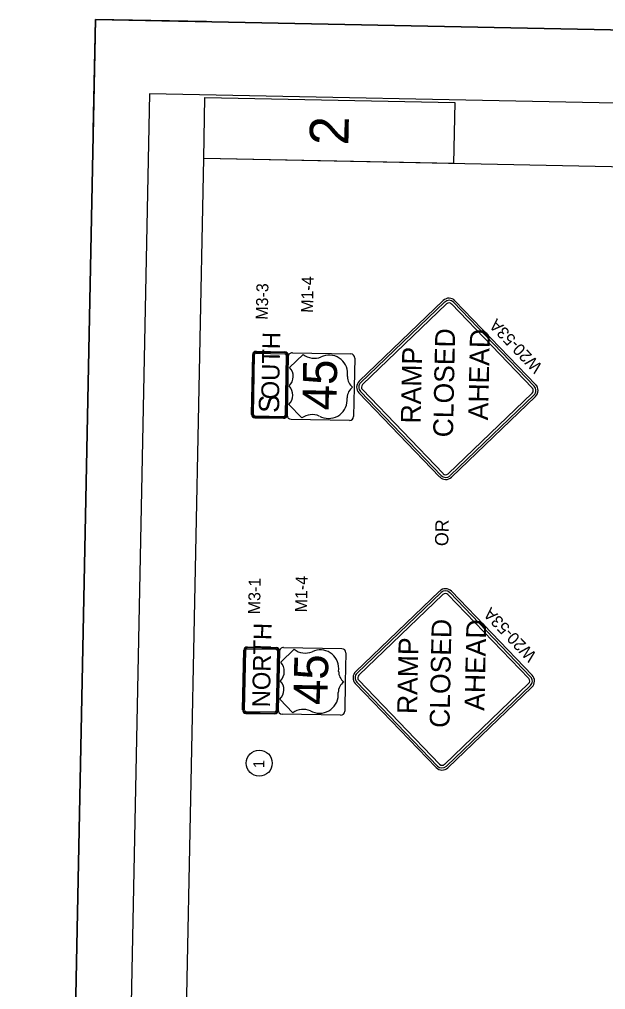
# Model space of a CAD drawing. Extents: x 345549 to 379569, y 127949 to 230467.
# Drawn here: x 345549 to 353466, y 217351 to 230467 of the extents above; entities that cross this region are included whole.
import ezdxf

# ---------------------------------------------------------------- set-up
doc = ezdxf.new("R2010")
doc.units = 0
for name, color, linetype in [('CA-TEXT', 7, 'Continuous'), ('P_RDWY_Text', 7, 'Continuous'), ('P_SGN_Cell', 7, 'Continuous'), ('PLT_Sheet_Border', 7, 'Continuous'), ('PLT_Sheet_Info', 7, 'Continuous')]:
    doc.layers.add(name, color=color, linetype=linetype)

msp = doc.modelspace()

# ---------------------------------------------------------------- linework, layer by layer
at = {"layer": 'CA-TEXT'}
msp.add_circle((348788, 220412), 176, dxfattribs=at)
at = {"layer": 'P_RDWY_Text'}
msp.add_lwpolyline([(345549, 179477), (346576, 230467), (379569, 229803), (378542, 178813)], close=True, dxfattribs=at)
at = {"layer": 'P_SGN_Cell'}
for p, q in [((348684, 225127), (348700, 225937)), ((348695, 225127), (348711, 225937)), ((348710, 225127), (348726, 225937)), ((348745, 225955), (349135, 225947)), ((348746, 225981), (349136, 225974)), ((348746, 225970), (349136, 225962)), ((349154, 225928), (349137, 225118)), ((349169, 225928), (349152, 225118)), ((349180, 225928), (349164, 225118)), ((349164, 225118), (349180, 225905)), ((349380, 225936), (349198, 225761)), ((349237, 225960), (350024, 225944)), ((350079, 225887), (350071, 225493)), ((350079, 225887), (350079, 225887)), ((349981, 225638), (349982, 225674)), ((350071, 225493), (350063, 225100)), ((349975, 225317), (349975, 225352)), ((349188, 225261), (349362, 225079)), ((348728, 225108), (349118, 225100)), ((348728, 225093), (349118, 225085)), ((348728, 225082), (349118, 225074)), ((350006, 225045), (349219, 225060)), ((348563, 221131), (348580, 221941)), ((348575, 221131), (348591, 221941)), ((348590, 221131), (348606, 221941)), ((348625, 221974), (349015, 221966)), ((348625, 221959), (349015, 221951)), ((348626, 221985), (349016, 221977)), ((349033, 221932), (349017, 221122)), ((349048, 221932), (349032, 221122)), ((349060, 221931), (349043, 221122)), ((349260, 221951), (349078, 221776)), ((349117, 221975), (349904, 221960)), ((349044, 221133), (349059, 221920)), ((349959, 221902), (349951, 221508)), ((349959, 221902), (349959, 221902)), ((349861, 221653), (349862, 221689)), ((349951, 221508), (349943, 221115)), ((349067, 221276), (349242, 221094)), ((349855, 221332), (349855, 221367)), ((348608, 221112), (348998, 221104)), ((348608, 221097), (348998, 221089)), ((348608, 221085), (348998, 221078)), ((349886, 221060), (349099, 221076))]:
    msp.add_line(p, q, dxfattribs=at)
for points in [[(351274, 226667), (350138, 225576)], [(352523, 225529), (351432, 226664)], [(351293, 226647), (350157, 225556)], [(351318, 226621), (350182, 225530)], [(352476, 225484), (351386, 226620)], [(352502, 225509), (351411, 226645)], [(350134, 225417), (351225, 224281)], [(350155, 225437), (351246, 224301)], [(350181, 225462), (351272, 224326)], [(351340, 224324), (352476, 225415)], [(351365, 224299), (352501, 225390)], [(351385, 224278), (352520, 225369)], [(351225, 222739), (350089, 221648)], [(351245, 222719), (350109, 221627)], [(352454, 221581), (351363, 222717)], [(352474, 221601), (351383, 222736)], [(351269, 222693), (350134, 221602)], [(352428, 221556), (351337, 222692)], [(350086, 221489), (351177, 220353)], [(350106, 221509), (351197, 220373)], [(350132, 221534), (351223, 220398)], [(351291, 220396), (352427, 221487)], [(351316, 220371), (352452, 221462)], [(351336, 220350), (352472, 221441)]]:
    msp.add_lwpolyline(points, dxfattribs=at)
for centre, radius, start, end in [((351351, 226586), 112, 43.8462, 133.8462), ((351351, 226586), 83.9, 43.8462, 133.8462), ((351351, 226586), 48.2, 43.8462, 133.8462), ((348745, 225936), 45, 88.8462, 178.8462), ((348745, 225936), 33.7, 88.8462, 178.8462), ((348745, 225936), 18.7, 88.8462, 178.8462), ((349135, 225929), 18.7, 358.8462, 88.8462), ((349135, 225929), 45, 358.8462, 88.8462), ((349135, 225929), 33.7, 358.8462, 88.8462), ((349236, 225904), 56.2, 88.8462, 178.8462), ((349530, 226136), 250, 233.1143, 291.9873), ((349732, 225679), 250, 358.8462, 115.6928), ((350023, 225888), 56.2, 358.8462, 88.8462), ((349068, 225639), 179, 314.4191, 43.2734), ((350162, 225635), 181, 179.1885, 231.634), ((349063, 225389), 179, 314.4191, 43.2734), ((350156, 225348), 181, 126.0584, 178.5039), ((350216, 225495), 112, 133.8443, 223.8462), ((350216, 225495), 83.9, 133.8443, 223.8462), ((350216, 225495), 48.2, 133.8443, 223.8462), ((352442, 225450), 48.2, 313.8534, 44.4971), ((352442, 225450), 83.9, 313.8534, 44.4971), ((352442, 225450), 112, 313.8534, 44.4971), ((349725, 225322), 250, 240.0981, 358.8463), ((348729, 225127), 45, 179.6119, 268.8462), ((348729, 225127), 33.7, 178.8462, 268.8462), ((348729, 225127), 18.7, 178.8462, 268.8462), ((349119, 225119), 33.7, 268.8462, 358.8462), ((349119, 225119), 18.7, 268.8462, 358.8462), ((349119, 225119), 45, 268.8462, 358.8462), ((349220, 225117), 56.2, 178.8462, 268.8462), ((349505, 224874), 250, 67.7159, 124.7982), ((350007, 225101), 56.2, 268.8462, 358.8462), ((351307, 224359), 83.9, 223.8462, 313.8462), ((351307, 224359), 48.2, 223.8462, 313.8462), ((351307, 224359), 112, 223.8462, 313.8462), ((351303, 222658), 112, 43.8462, 133.8462), ((351303, 222658), 83.9, 43.8462, 133.8462), ((351303, 222658), 48.2, 43.8462, 133.8462), ((348625, 221940), 45, 88.8462, 178.8462), ((348625, 221940), 33.7, 88.8462, 178.8462), ((348625, 221940), 18.7, 88.8462, 178.8462), ((349015, 221932), 33.7, 358.8462, 88.8462), ((349015, 221932), 18.7, 358.8462, 88.8462), ((349015, 221932), 45, 358.8462, 88.8462), ((349116, 221919), 56.2, 88.8462, 178.8462), ((349410, 222151), 250, 233.1143, 291.9873), ((349612, 221694), 250, 358.8462, 115.6928), ((349903, 221903), 56.2, 358.8462, 88.8462), ((348948, 221654), 179, 314.4191, 43.2734), ((350042, 221651), 181, 179.1885, 231.634), ((350167, 221567), 112, 133.8443, 223.8462), ((350167, 221567), 83.9, 133.8443, 223.8462), ((350167, 221567), 48.2, 133.8443, 223.8462), ((352394, 221522), 48.2, 313.8534, 44.4971), ((352394, 221522), 83.9, 313.8534, 44.4971), ((352394, 221522), 112, 313.8534, 44.4971), ((348942, 221404), 179, 314.4191, 43.2734), ((350036, 221363), 181, 126.0584, 178.5039), ((349605, 221337), 250, 240.0981, 358.8463), ((348609, 221130), 45, 179.6119, 268.8462), ((348609, 221130), 33.7, 178.8462, 268.8462), ((348609, 221130), 18.7, 178.8462, 268.8462), ((348998, 221123), 33.7, 268.8462, 358.8462), ((348998, 221123), 18.7, 268.8462, 358.8462), ((348998, 221123), 45, 268.8462, 358.8462), ((349100, 221132), 56.2, 178.8462, 268.8462), ((349385, 220889), 250, 67.7159, 124.7982), ((349887, 221116), 56.2, 268.8462, 358.8462), ((351258, 220431), 83.9, 223.8462, 313.8462), ((351258, 220431), 48.2, 223.8462, 313.8462), ((351258, 220431), 112, 223.8462, 313.8462)]:
    msp.add_arc(centre, radius, start, end, dxfattribs=at)
at = {"layer": 'PLT_Sheet_Border'}
for points in [[(378542, 178813), (379569, 229803), (346576, 230467), (345549, 179477)], [(377800, 179188), (378799, 228828), (347306, 229462), (346306, 179822)]]:
    msp.add_lwpolyline(points, close=True, dxfattribs=at)
at = {"layer": 'PLT_Sheet_Info'}
for p, q in [((346546, 228967), (346576, 230467)), ((348076, 230437), (346576, 230467)), ((347087, 181344), (348038, 228585)), ((378032, 227981), (348038, 228585))]:
    msp.add_line(p, q, dxfattribs=at)
msp.add_lwpolyline([(348038, 228585), (348055, 229410), (351429, 229342), (351413, 228517)], close=True, dxfattribs=at)

# ---------------------------------------------------------------- texts
at = {"layer": 'CA-TEXT'}
for s, height, p in [('OR', 180, (351341, 223345)), ('1', 150, (348856, 220345))]:
    msp.add_text(s, height=height, rotation=88.8468, dxfattribs=at).set_placement(p)
at = {"layer": 'P_SGN_Cell'}
for s, height, rotation, p in [('M1-4', 162, 88.8462, (349514, 226499)), ('M3-3', 162, 88.8462, (348903, 226405)), ('W20-53A', 162, 133.8462, (352624, 225780)), ('CLOSED', 267.9, 88.8462, (351405, 224815)), ('AHEAD', 267.9, 88.8462, (351879, 225046)), ('OUTH', 240, 88.8462, (349055, 225329)), ('RAMP', 267.9, 88.8462, (350968, 225002)), ('45', 460, 88.8462, (349829, 225180)), ('S', 274, 88.8462, (349055, 225145)), ('M3-1', 162, 88.8462, (348799, 222423)), ('M1-4', 162, 88.8462, (349433, 222449)), ('W20-53A', 162, 133.8462, (352545, 221877)), ('CLOSED', 267.9, 88.8462, (351357, 220887)), ('AHEAD', 267.9, 88.8462, (351830, 221118)), ('NORTH', 240, 88.8462, (348932, 221165)), ('RAMP', 267.9, 88.8462, (350919, 221074)), ('45', 460, 88.8462, (349709, 221195))]:
    msp.add_text(s, height=height, rotation=rotation, dxfattribs=at).set_placement(p)
at = {"layer": 'PLT_Sheet_Info'}
msp.add_text('2', height=525, rotation=88.8462, dxfattribs=at).set_placement((349992, 228762))

doc.saveas('drawing.dxf')
